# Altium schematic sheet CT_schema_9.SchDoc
size 277 x 170 mm
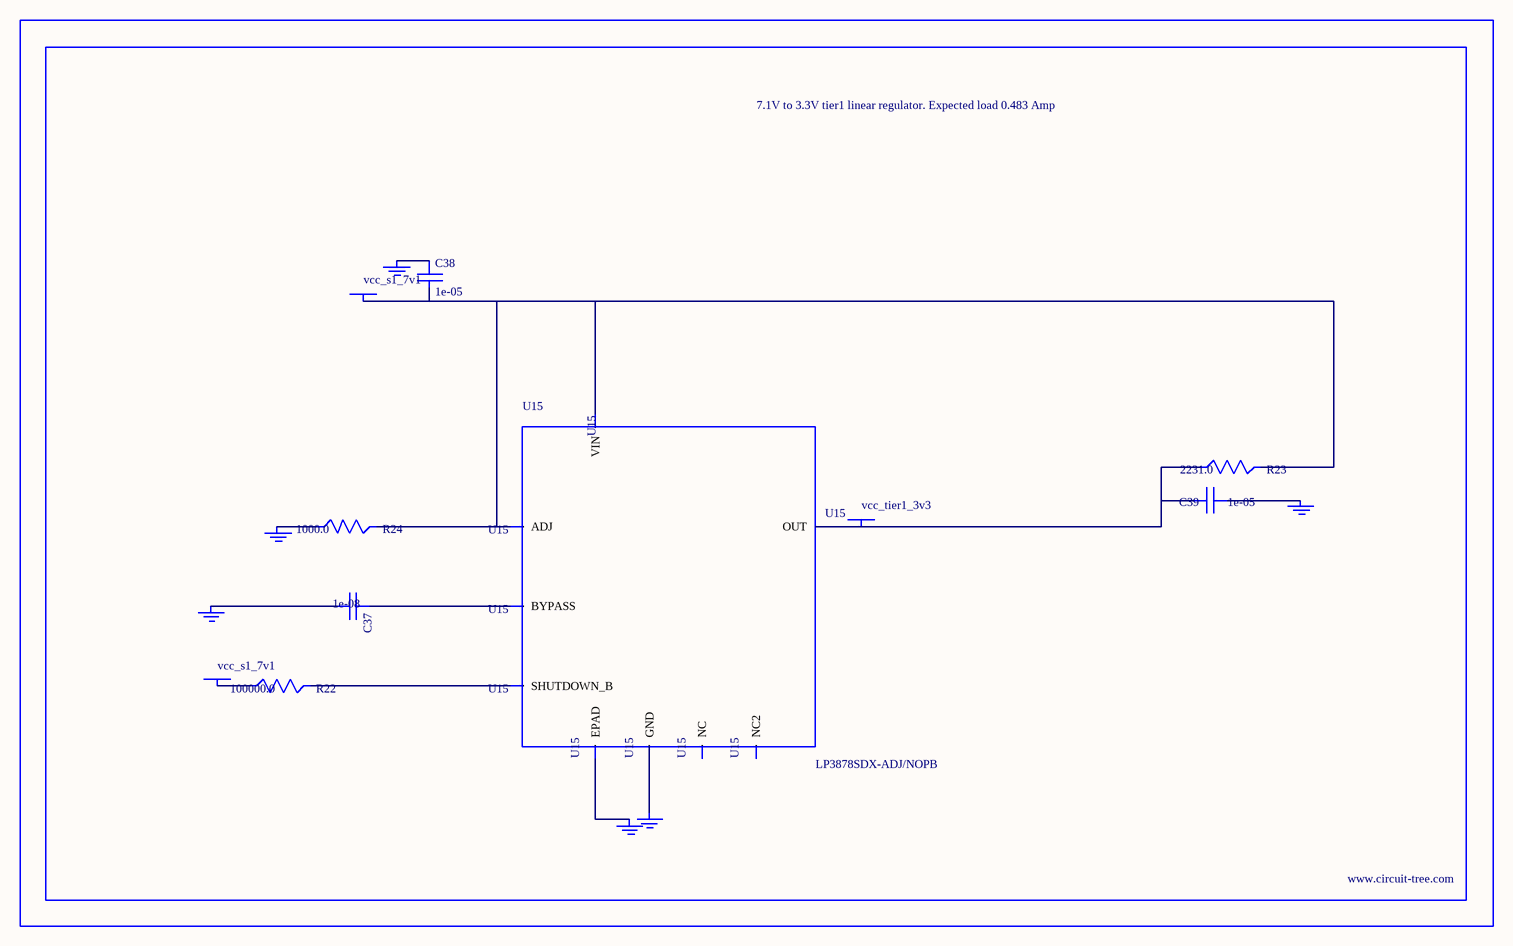
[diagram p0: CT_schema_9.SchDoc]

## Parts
BORDER8  (no value)
C37  1e-08  [C0402]
C38  1e-05  [C1206]
C39  1e-05  [C1210]
GND_INSTANCE_8_0  (no value)
GND_INSTANCE_8_1  (no value)
GND_INSTANCE_8_2  (no value)
GND_INSTANCE_8_3  (no value)
GND_INSTANCE_8_4  (no value)
GND_INSTANCE_8_5  (no value)
POWER_INSTANCE_8_0  vcc_s1_7v1
POWER_INSTANCE_8_1  vcc_s1_7v1
POWER_INSTANCE_8_2  vcc_tier1_3v3
R22  100000.0  [R0603]
R23  2231.0  [R0603]
R24  1000.0  [R0603]
U15  LP3878SDX-ADJ/NOPB  [WSON-8]

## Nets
NetC37_1: C37.1 U15.1(BYPASS)
NetC37_2: C37.2 GND_INSTANCE_8_0.0(GND)
NetC38_1: C38.1 GND_INSTANCE_8_1.0(GND)
NetC38_2: C38.2 POWER_INSTANCE_8_0.0(PWR) R23.2 R24.2 U15.4(VIN) U15.6(ADJ)
NetC39_1: C39.1 GND_INSTANCE_8_2.0(GND)
NetC39_2: C39.2 POWER_INSTANCE_8_2.0(PWR) R23.1 U15.5(OUT)
NetGND_INSTANCE_8_3_0: GND_INSTANCE_8_3.0(GND) R24.1
NetGND_INSTANCE_8_4_0: GND_INSTANCE_8_4.0(GND) U15.PAD(EPAD)
NetGND_INSTANCE_8_5_0: GND_INSTANCE_8_5.0(GND) U15.3(GND)
NetPOWER_INSTANCE_8_1_0: POWER_INSTANCE_8_1.0(PWR) R22.1
NetR22_2: R22.2 U15.8(SHUTDOWN_B)

Not connected (* = marked no-connect by the designer): U15 2(NC) 7(NC2)

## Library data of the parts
BORDER8 = BORDER_PAGE8
C37 = C0402C103K3RAC
C38 = C1206C106K3RACTU
C39 = GRM32DR61E106MA12L
GND_INSTANCE_8_0-GND_INSTANCE_8_5 = GND
POWER_INSTANCE_8_0-POWER_INSTANCE_8_2 = PWR
R22 = RC0603JR-07100KL
R23 = R23
R24 = RC0603JR-071KL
